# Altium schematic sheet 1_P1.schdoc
size 429 x 307 mm; Symbol: Drawing-Symbol_A4; Device: Drawing-Symbol_A4; @Project Name: odin8266; @Page Count: 1; @Update Date: 2026-06-03; @Create Date: 2026-05-24; @Schematic Name: Schematic1; @Page No: 1; @Page Name: P1; Company: EasyEDA.com; Version: V1.0; Page Size: A4; @Create Time: 21:53:29; @Update Time: 00:31:02; Width: 1655; Height: 1170; Region Start: 1; X Region Count: 6; Y Region Count: 4; Blade Width: 10; Title Block Position: 3; @Board Name: Board1
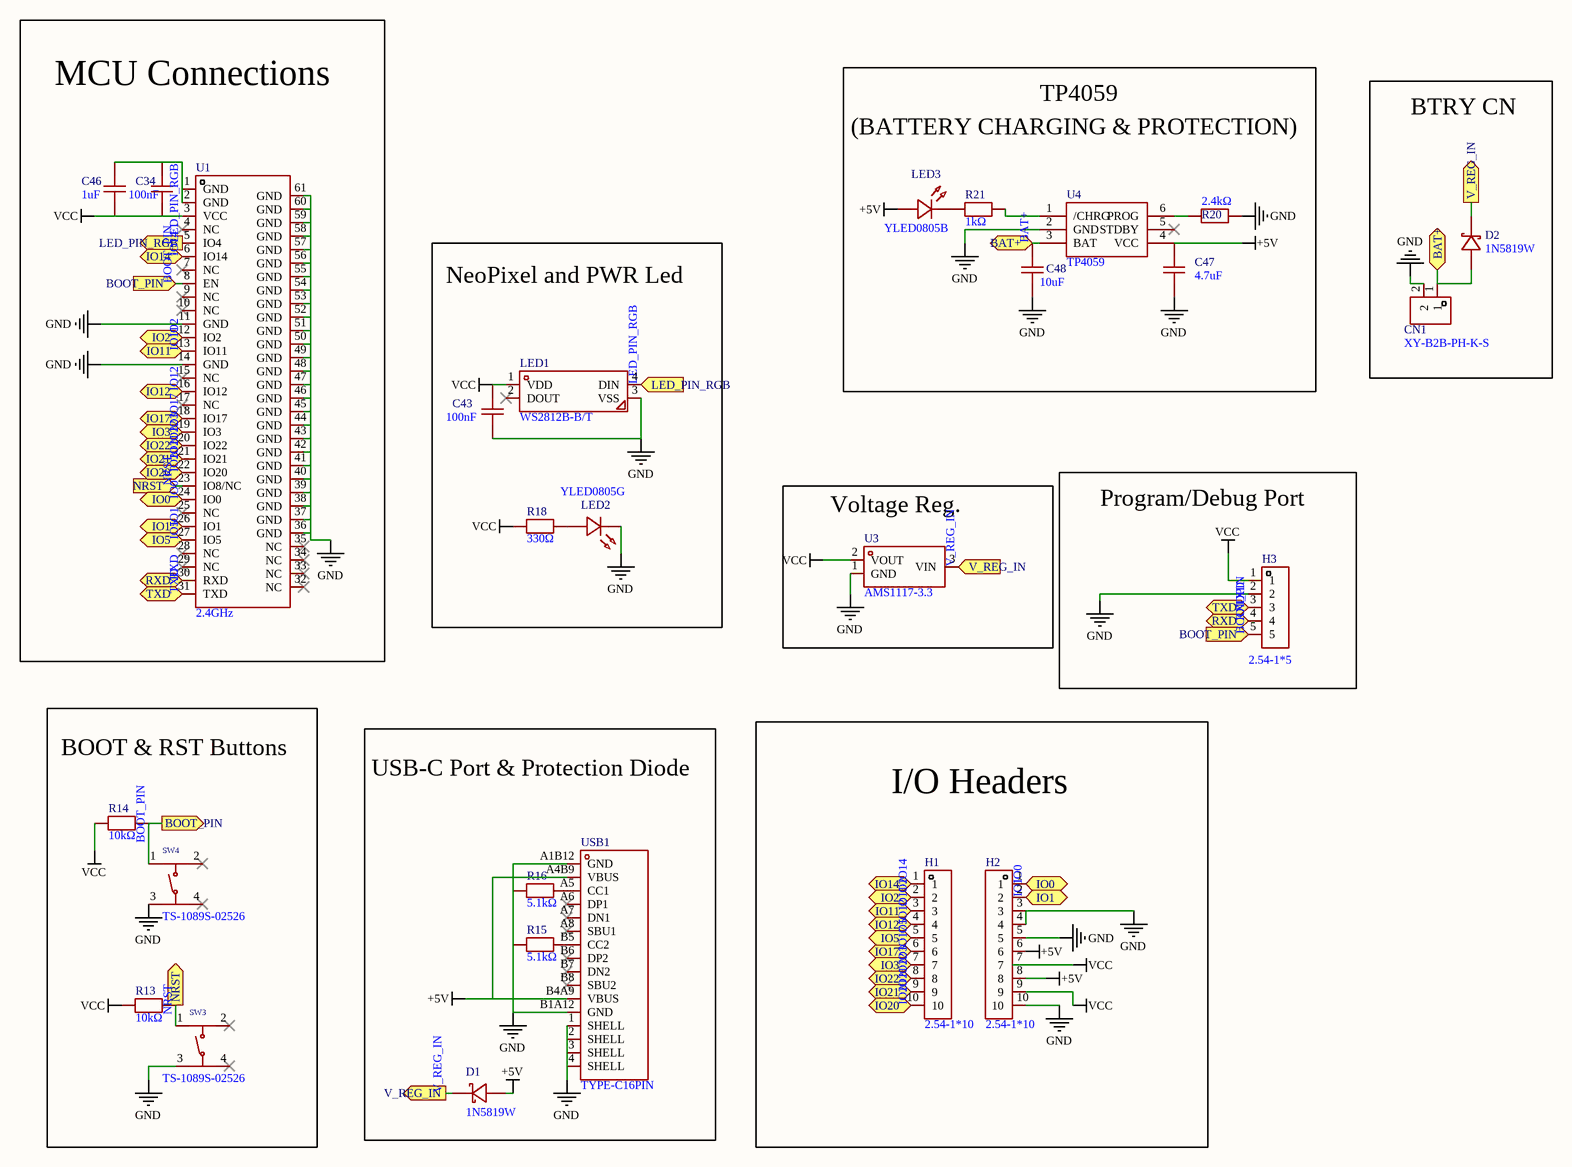
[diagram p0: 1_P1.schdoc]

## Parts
C34  100nF  [C0603]
C43  100nF  [C0603]
C46  1uF  [C0603]
C47  4.7uF  [C0603]
C48  10uF  [C0603]
CN1  XY-B2B-PH-K-S  [CONN-TH_B2B-PH-K-S]
D1  1N5819W  [SOD-123_L2.7-W1.6-LS3.7-RD]
D2  1N5819W  [SOD-123_L2.7-W1.6-LS3.7-RD]
H1  2.54-1*10  [HDR-TH_10P-P2.54-V-M]
H2  2.54-1*10  [HDR-TH_10P-P2.54-V-M]
H3  2.54-1*5  [HDR-TH_5P-P2.54-V-M]
LED1  WS2812B-B/T  [LED-SMD_4P-L5.0-W5.0-TL_WS2812B-B]
LED2  YLED0805G  [LED0805-FD-GREEN]
LED3  YLED0805B  [LED0805-RD]
R13  10kΩ  [R0603]
R14  10kΩ  [R0603]
R15  5.1kΩ  [R0603]
R16  5.1kΩ  [R0603]
R18  330Ω  [R0603]
R20  2.4kΩ  [R0603]
R21  1kΩ  [R0603]
SW3  TS-1089S-02526  [SW-SMD_4P-L4.2-W3.3-P2.15-LS5.1]
SW4  TS-1089S-02526  [SW-SMD_4P-L4.2-W3.3-P2.15-LS5.1]
U1  2.4GHz  [WIFIM-SMD_61P-CUSTOMBRUH]
U3  AMS1117-3.3  [SOT-223-3_L6.5-W3.4-P2.30-LS7.0-BR-1]
U4  TP4059  [SOT-23-6_L2.9-W1.6-P0.95-LS2.8-BR]
USB1  TYPE-C16PIN  [USB-C-SMD_TYPE-C16PIN]

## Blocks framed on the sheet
MCU Connections: C34 C46 U1
BTRY CN: CN1 D2
NeoPixel and PWR Led: C43 LED1 LED2 R18
Voltage Reg.: U3
Program/Debug Port: H3
BOOT & RST Buttons: R13 R14 SW3 SW4
USB-C Port & Protection Diode: D1 R15 R16 USB1
I/O Headers: H1 H2

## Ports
BAT+ (bidir), BOOT_PIN (in), BOOT_PIN (out), IO0 (bidir), IO1 (bidir), IO2 (bidir), IO3 (bidir), IO5 (bidir), IO11 (bidir), IO12 (bidir), IO14 (bidir), IO17 (bidir), IO20 (bidir), IO21 (bidir), IO22 (bidir), LED_PIN_RGB (in), LED_PIN_RGB (out), NRST (in), NRST (out), RXD (bidir), TXD (bidir), V_REG_IN (in), V_REG_IN (out)

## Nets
+5V: C47.1 D1.2(A) H2.6 H2.8 LED3.2(A) U4.4(VCC) USB1.A4B9(VBUS) USB1.B4A9(VBUS)
GND: C43.1 C47.2 C48.1 CN1.2 H2.3 H2.4 H2.5 H2.10 H3.2 LED1.3(VSS) LED2.2(K) R15.1 R16.1 R20.2 SW3.3 SW4.3 U1.11(GND) U1.14(GND) U1.36(GND) U1.37(GND) U1.38(GND) U1.39(GND) U1.40(GND) U1.41(GND) U1.42(GND) U1.43(GND) U1.44(GND) U1.45(GND) U1.46(GND) U1.47(GND) U1.48(GND) U1.49(GND) U1.50(GND) U1.51(GND) U1.52(GND) U1.53(GND) U1.54(GND) U1.55(GND) U1.56(GND) U1.57(GND) U1.58(GND) U1.59(GND) U1.60(GND) U1.61(GND) U3.1(GND) U4.2(GND) USB1.1(SHELL) USB1.2(SHELL) USB1.3(SHELL) USB1.4(SHELL) USB1.A1B12(GND) USB1.B1A12(GND)
VCC: C34.1 C43.2 C46.2 H2.7 H2.9 H3.1 LED1.1(VDD) R13.1 R14.1 R18.1 U1.3(VCC) U3.2(VOUT)
BAT+: C48.2 CN1.1 D2.2(A) U4.3(BAT) ; port BAT+
BOOT_PIN: H3.5 R14.2 SW4.1 U1.8(EN) ; port BOOT_PIN
IO0: H2.1 U1.24(IO0) ; port IO0
IO1: H2.2 U1.26(IO1) ; port IO1
IO2: H1.2 U1.12(IO2) ; port IO2
IO3: H1.7 U1.19(IO3) ; port IO3
IO5: H1.5 U1.27(IO5) ; port IO5
IO11: H1.3 U1.13(IO11) ; port IO11
IO12: H1.4 U1.16(IO12) ; port IO12
IO14: H1.1 U1.6(IO14) ; port IO14
IO17: H1.6 U1.18(IO17) ; port IO17
IO20: H1.10 U1.22(IO20) ; port IO20
IO21: H1.9 U1.21(IO21) ; port IO21
IO22: H1.8 U1.20(IO22) ; port IO22
LED_PIN_RGB: LED1.4(DIN) U1.5(IO4) ; port LED_PIN_RGB
NRST: R13.2 SW3.1 U1.23(IO8/NC) ; port NRST
RXD: H3.4 U1.30(RXD) ; port RXD
TXD: H3.3 U1.31(TXD) ; port TXD
V_REG_IN: D1.1(C) D2.1(C) U3.3(VIN) ; port V_REG_IN
NetC34_2: C34.2 C46.1 U1.1(GND) U1.2(GND)
NetLED2_1: LED2.1(A) R18.2
NetLED3_1: LED3.1(K) R21.1
NetR15_2: R15.2 USB1.B5(CC2)
NetR16_2: R16.2 USB1.A5(CC1)
NetR20_1: R20.1 U4.6(PROG)
NetR21_2: R21.2 U4.1(/CHRG)

Not connected (* = marked no-connect by the designer): LED1 2(DOUT)*; SW3 2* 4*; SW4 2* 4*; U1 4(NC)* 7(NC)* 9(NC)* 10(NC)* 15(NC)* 17(NC)* 25(NC)* 28(NC)* 29(NC)* 32(NC)* 33(NC)* 34(NC)* 35(NC)*; U4 5(STDBY)*; USB1 A6(DP1)* A7(DN1)* A8(SBU1)* B6(DP2)* B7(DN2)* B8(SBU2)*

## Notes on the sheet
- (BATTERY CHARGING & PROTECTION)
- TP4059

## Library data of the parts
C34 C43 = FCC0603B104K500CT: Manufacturer: FOJAN(富捷); Add into BOM: yes; Tolerance: ±10%; Voltage Rating: 50V; Temperature Coefficient: X7R
C46 = CGA0603X5R105K500JT: Manufacturer: HRE(芯声); Add into BOM: yes; Tolerance: ±10%; Voltage Rating: 50V; Temperature Coefficient: X5R
C47 = TCC0603X5R475K160CT: Manufacturer: CCTC(三环); Add into BOM: yes; Tolerance: ±10%; Voltage Rating: 16V; Temperature Coefficient: X5R
C48 = TCC0603X5R106K100CT: Manufacturer: CCTC(三环); Add into BOM: yes; Tolerance: ±10%; Voltage Rating: 10V; Temperature Coefficient: X5R
CN1 = XY-B2B-PH-K-S: Manufacturer: XYECONN(辛译); Add into BOM: yes; Pins Structure: 1x2P; Pitch: 2mm; Number of PINs Per Row: 2; Current Rating: 2A; Voltage Rating: 250V; Plastic Material: PA66; Flame Retardant Rating: UL94V-0
D1 D2 = 1N5819W_C41431973: Manufacturer: GOODWORK(固得沃克); Add into BOM: yes; Diode Configuration: Independent; Voltage - Forward(Vf@If): 580mV@1A; Voltage - DC Reverse(Vr): 40V; Current - Rectified: 1A; Reverse Leakage Current (Ir): 50uA@40V; Operating Junction Temperature Range: -65℃~+125℃; Non-Repetitive Peak Forward Surge Current: 9A
H1 H2 = 2.54-1*10: Manufacturer: ZHOURI(洲日); Add into BOM: yes; Pin Structure: 1x10P; Pitch: 2.54mm; Circluar Pins/Square Pins: Pin Header; Current Rating: 2.5A
H3 = 2.54-1*5: Manufacturer: ZHOURI(洲日); Add into BOM: yes; Pin Structure: 1x5P; Pitch: 2.54mm; Circluar Pins/Square Pins: Pin Header; Current Rating: 2.5A
LED1 = WS2812B-B/T: Manufacturer: worldsemi; Symbol: WS2812B-B/W; Add into BOM: yes; Wavelength: 520nm；471nm；621nm; Luminous Intensity: R:300mcd~500mcd；B:200mcd~300mcd；G:600mcd~1000mcd; Fixed-Frequency Pwm Mode: 2kHz; Data Transmission Rate: 800Kbit/s; Quiescent Current: 0.6mA; Peak Wavelength: G:520nm；R:621nm；B:471nm
LED2 = YLED0805G: Manufacturer: YONGYUTAI(永裕泰); Add into BOM: yes; Lamp Holder Type: 2mm x 1.25mm square LED; Illumination Color: Emerald Green; Voltage - Forward(Vf): 2.4V~3.1V; Power(Watts): 70mW; Forward Current: 20mA; Wavelength - Dominant: 516nm~534nm; Peak Wavelength: 525nm; Diode Configuration: Discrete Diode; Lens Color: Water Clear; Luminous Intensity: 430mcd; Viewing Angle: 120°
LED3 = YLED0805B: Manufacturer: YONGYUTAI(永裕泰); Add into BOM: yes; Illumination Color: Blue; Voltage - Forward(Vf): 2.7V~3.1V; Forward Current: 25mA; Wavelength - Dominant: 457nm~475nm; Diode Configuration: Discrete Diode; Luminous Intensity: 80mcd; Viewing Angle: 120°
R13 R14 = FRC0603J103 TS: Manufacturer: FOJAN(富捷); Add into BOM: yes; Tolerance: ±5%; Power(Watts): 100mW; Voltage-Supply(Max): 75V; Temperature Coefficient: ±100ppm/℃
R15 R16 = FRC0603F5101TS: Manufacturer: FOJAN(富捷); Add into BOM: yes; Tolerance: ±1%; Power(Watts): 100mW; Voltage-Supply(Max): 75V; Temperature Coefficient: ±100ppm/℃
R18 = FRC0603J331 TS: Manufacturer: FOJAN(富捷); Add into BOM: yes; Tolerance: ±5%; Power(Watts): 100mW; Voltage-Supply(Max): 75V; Temperature Coefficient: ±100ppm/℃
R20 = FRC0603F2401TS: Manufacturer: FOJAN(富捷); Add into BOM: yes; Tolerance: ±1%; Power(Watts): 100mW; Voltage-Supply(Max): 75V; Temperature Coefficient: ±100ppm/℃
R21 = FRC0603J102 TS: Manufacturer: FOJAN(富捷); Add into BOM: yes; Tolerance: ±5%; Power(Watts): 100mW; Voltage-Supply(Max): 75V; Temperature Coefficient: ±100ppm/℃
SW3 SW4 = TS-1089S-02526: Manufacturer: XUNPU(讯普); Add into BOM: yes; Circuit: SPST; Actuator Style: Oval button; Switch Length: 4.2mm; Switch Width: 3.25mm; Switch Height: 2.5mm; Contact Current: 50mA; Voltage Rating (DC): 12V
U1 = Ai-WB2-M1-I: Manufacturer: Ai-Thinker(安信可); Utilized IC / Part: BL602 chip; Add into BOM: yes; Wireless Standard: 802.11b/g/n；BLE5.0; Interface Type: I2C；GPIO；UART；DAC；PWM；SPI；ADC; Antenna Type: IPEX interface; Output Power: 16dBm; Voltage - Supply: 3.3V; Receive  Current: 64mA; Send  Current: 308mA; Sensitivity: -98dBm
U3 = AMS1117-3.3_C22459274: Manufacturer: 晶扬电子; Add into BOM: yes; Output Type: Fixed; Voltage - Supply: 12V; Output Voltage: 3.3V; Output Current: 1A; Power Supply Rejection Ratio (PSRR): 70dB@(120Hz); Voltage Dropout: 1.4V@(1A); Output Configuration: Positive; Number of Outputs: 1
U4 = TP4059: Manufacturer: TOPPOWER(南京拓微); Add into BOM: yes; The Chip Type: Charging IC; Voltage - Supply: 4V~9V; Charge Current - Max: 600mA; Charging Saturation Voltage: 4.2V; Type of Battery: Lithium Battery; Number of Cells: 1; Battery Temperature Detection: Not supported; Supply Current (Iq): 2uA
USB1 = TYPE-C16PIN: Manufacturer: SHOU HAN(首韩); Add into BOM: yes; Connector Type: Type-C; Gender: Female; Number of Contacts: 16P; Number of Ports: 1; Current Rating-Power: 3A; Voltage Rating: 30V; Connect-Disconnect Life: 10,000 Cycles; Detection color: Black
